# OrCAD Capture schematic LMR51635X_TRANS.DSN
size D
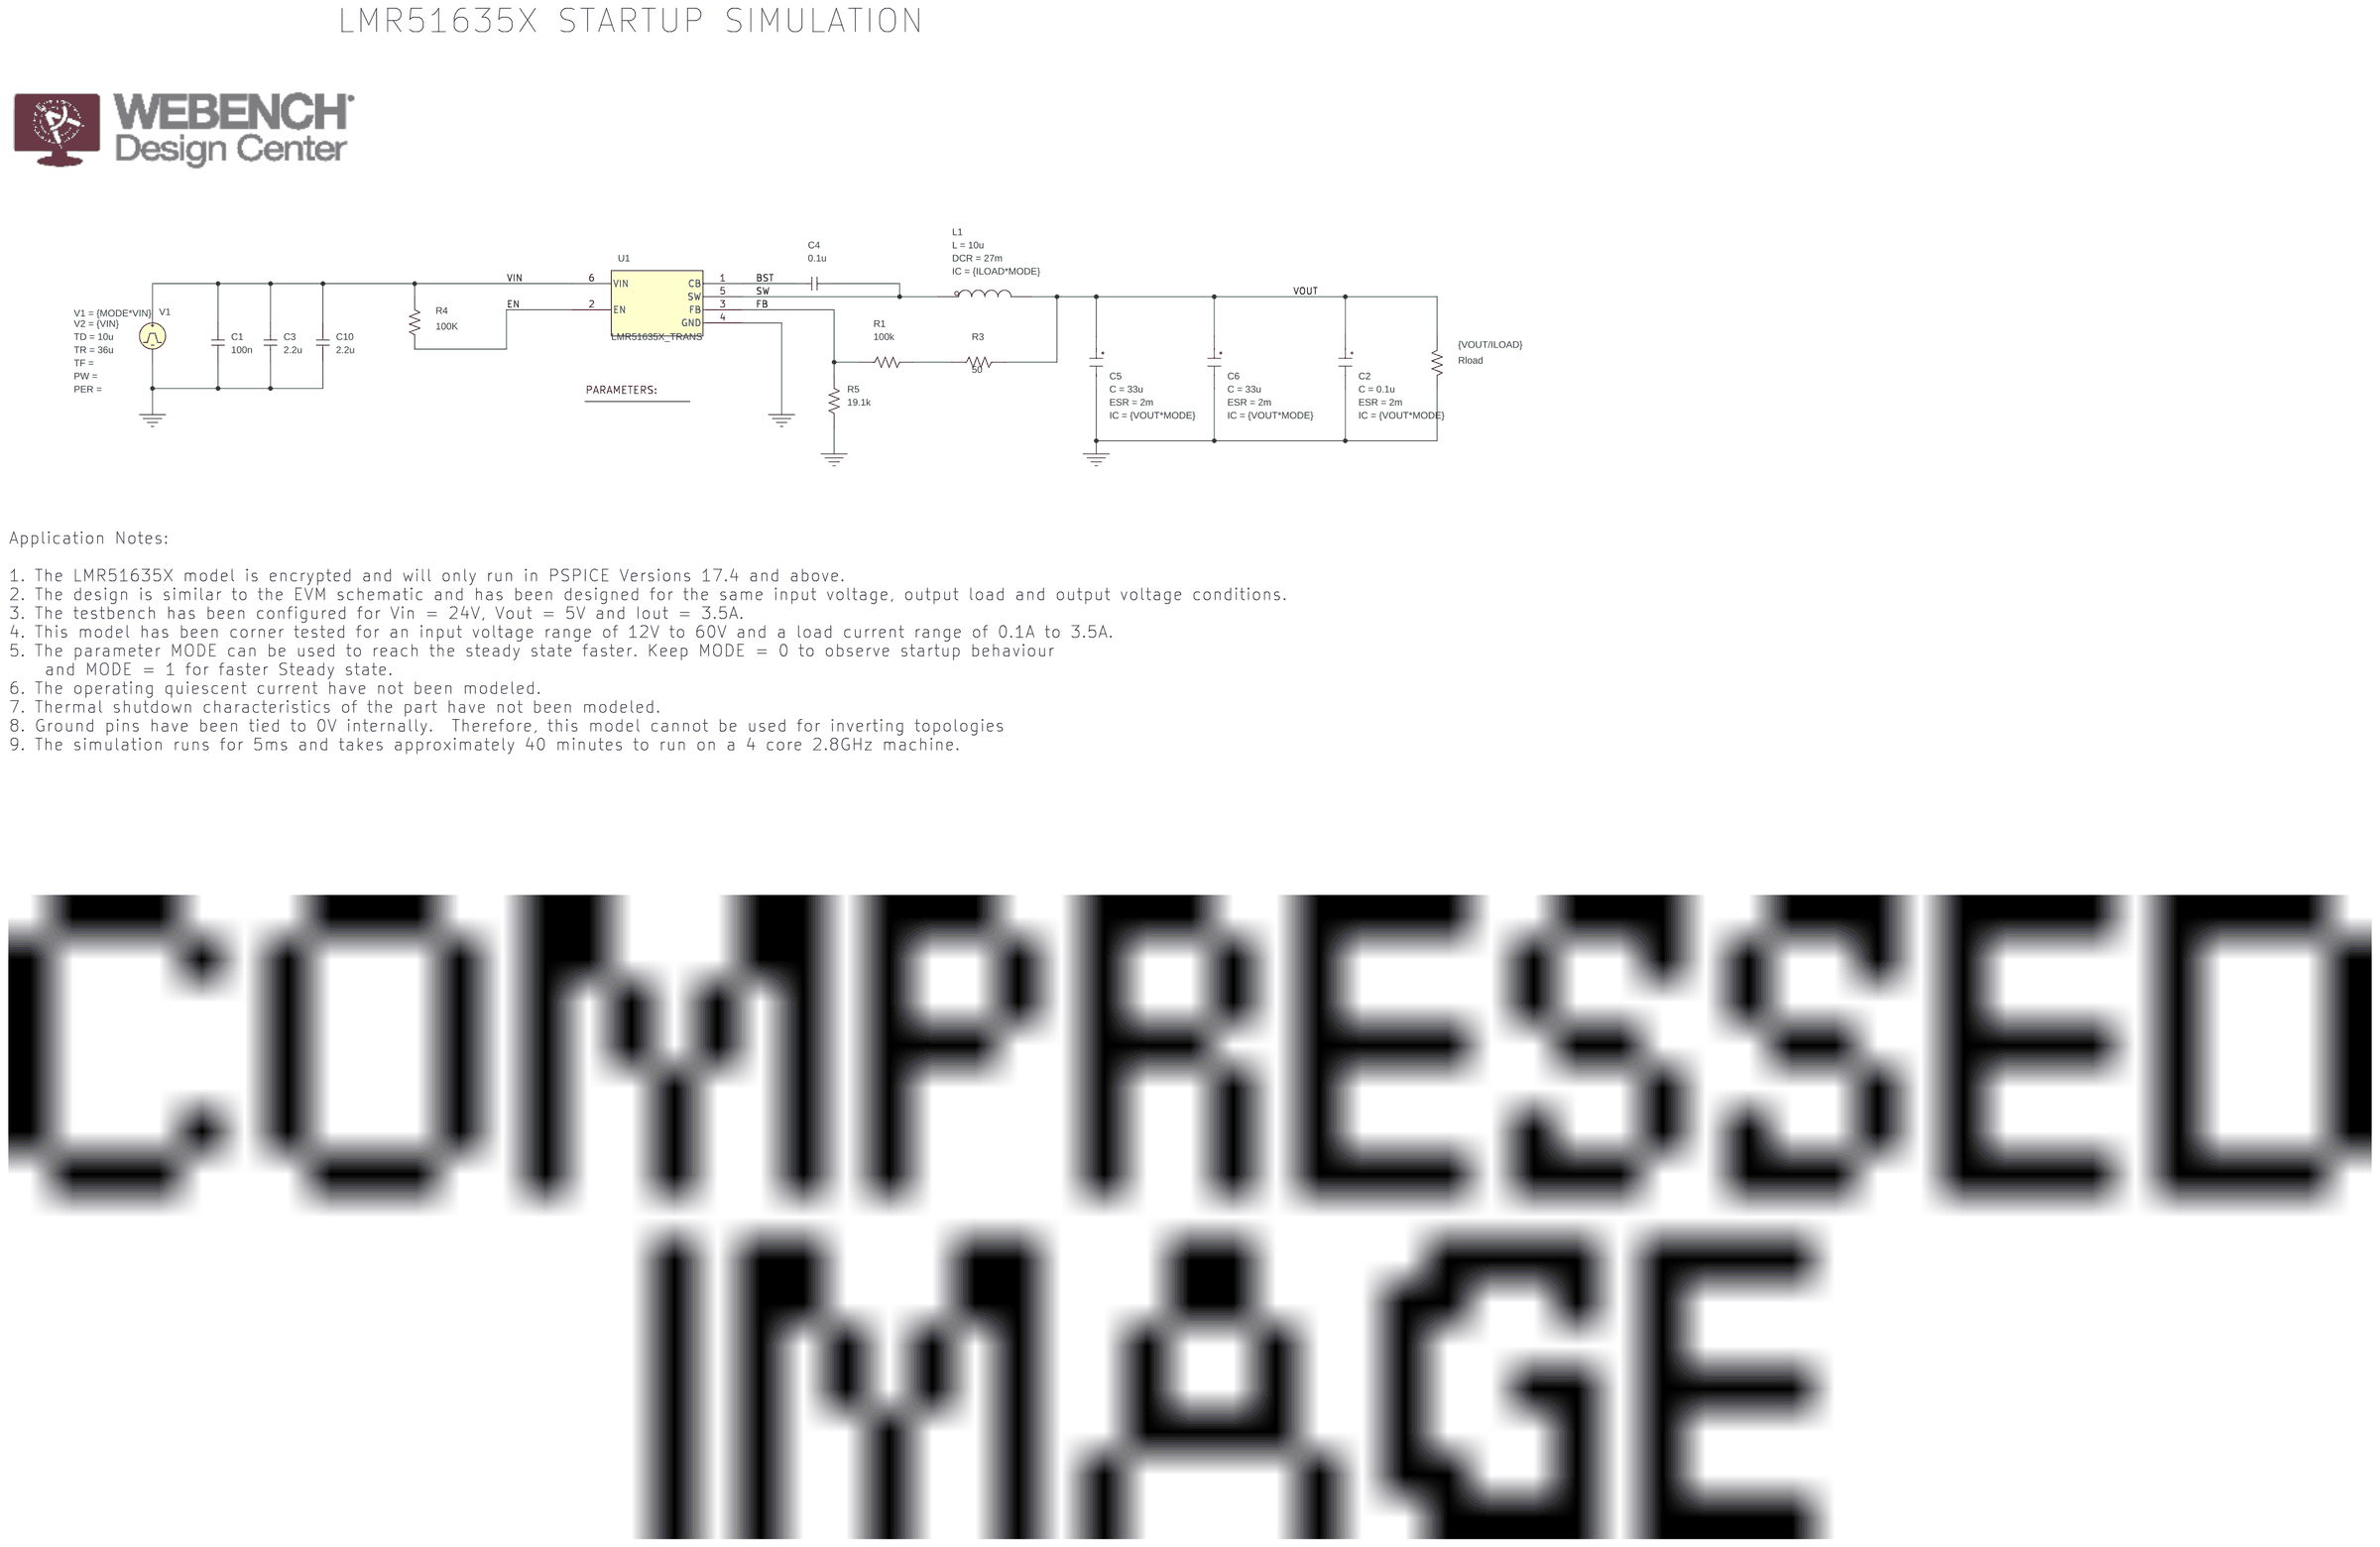
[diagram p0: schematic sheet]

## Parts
1  PARAM
C1  100n  [RAD/CK05]
C2  CESR
C3  2.2u  [RAD/CK05]
C4  0.1u  [RAD/CK05]
C5  CESR
C6  CESR
C10  2.2u  [RAD/CK05]
L1  LDCR
R1  100k  [RC05]
R3  50  [AX/RC05]
R4  100K  [AX/RC05]
R5  19.1k  [RC05]
Rload  {VOUT/ILOAD}  [AX/RC05]
U1  LMR51635X_TRANS
V1  VPULSE

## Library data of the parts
1 = PARAM: ILOAD: 3.5; MODE: 0; VIN: 24; VOUT: 5
C1 C3 C10 = C
C2 = CESR_0: C: 0.1u; ESR: 2m; IC: {VOUT*MODE}; PSpiceTemplate: X^@REFDES %IN %OUT @MODEL PARAMS:  ?C|C=@C||C=100u|  ?ESR|ESR=@ESR||ESR=0.01| ?X|X=@X||X=2|  ?IC|IC=@IC||IC=2|; X: 1
C4 = C: IC: -3.3
C5 C6 = CESR_0: C: 33u; ESR: 2m; IC: {VOUT*MODE}; PSpiceTemplate: X^@REFDES %IN %OUT @MODEL PARAMS:  ?C|C=@C||C=100u|  ?ESR|ESR=@ESR||ESR=0.01| ?X|X=@X||X=2|  ?IC|IC=@IC||IC=2|; X: 1
L1 = LDCR_0: DCR: 27m; IC: {ILOAD*MODE}; L: 10u; PSpiceTemplate: X^@REFDES %IN %OUT @MODEL PARAMS:  ?L|L=@L||L=1u|  ?DCR|DCR=@DCR||DCR=0.01| ?IC|IC=@IC||IC=0|
R1 R3-R5 Rload = R
U1 = LMR51635X_TRANS_2
V1 = VPULSE: TD: 10u; TR: 36u; V1: {MODE*VIN}; V2: {VIN}

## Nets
VIN: C1.2 C3.2 C10.2 R4.2 U1.6(VIN) V1.1(+)
0: C1.1 C2.3(OUT) C3.1 C5.3(OUT) C6.3(OUT) C10.1 R5.1 Rload.2 U1.4(GND) V1.2(-)
BST: C4.1 U1.1(CB)
EN: R4.1 U1.2(EN)
FB: R1.1 R5.2 U1.3(FB)
SW: C4.2 L1.1(IN) U1.5(SW)
VOUT: C2.1(IN) C5.1(IN) C6.1(IN) L1.3(OUT) R3.2 Rload.1
N16771643: R1.2 R3.1

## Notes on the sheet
- LMR51635X STARTUP SIMULATION
- Application Notes:
  1. The LMR51635X model is encrypted and will only run in PSPICE Versions 17.4 and above.
  2. The design is similar to the EVM schematic and has been designed for the same input voltage, output load and output voltage conditions.
  3. The testbench has been configured for Vin = 24V, Vout = 5V and Iout = 3.5A.
  4. This model has been corner tested for an input voltage range of 12V to 60V and a load current range of 0.1A to 3.5A.
  5. The parameter MODE can be used to reach the steady state faster. Keep MODE = 0 to observe startup behaviour
      and MODE = 1 for faster Steady state.
  6. The operating quiescent current have not been modeled.
  7. Thermal shutdown characteristics of the part have not been modeled.
  8. Ground pins have been tied to 0V internally.  Therefore, this model cannot be used for inverting topologies
  9. The simulation runs for 5ms and takes approximately 40 minutes to run on a 4 core 2.8GHz machine.
